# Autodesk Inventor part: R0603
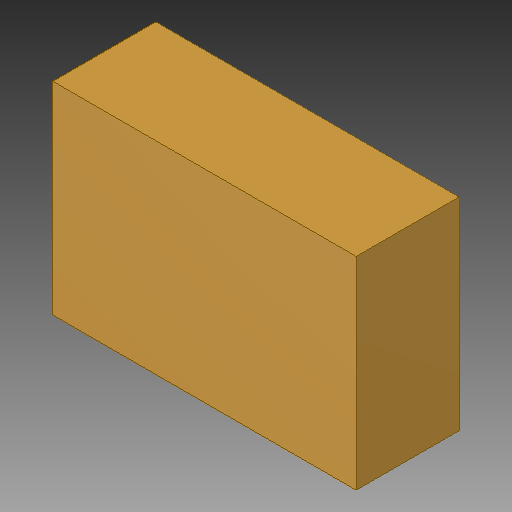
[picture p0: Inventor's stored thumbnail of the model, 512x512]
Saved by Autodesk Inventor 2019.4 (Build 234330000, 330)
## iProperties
Created: 2019-11
Part Number: R0603
Material: Generic
Document SubType Name: Modeling
Designer: Willist
Density: 1 g/cm^3
Appearance: R0603, R0603
Author: Willist
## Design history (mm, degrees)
sketch "R0603, R0603_5"
  geometry: L1 (-1.473, 0.983)-(1.473, 0.983); L2 (1.473, 0.983)-(1.473, -0.983); L3 (1.473, -0.983)-(-1.473, -0.983); L4 (-1.473, -0.983)-(-1.473, 0.983)
  constraints: 8 end point
extrude "Extrusion1" join sketch "R0603, R0603_5" distance "d0" = 1; taper "d1" = 0 deg
body "Solid1"
